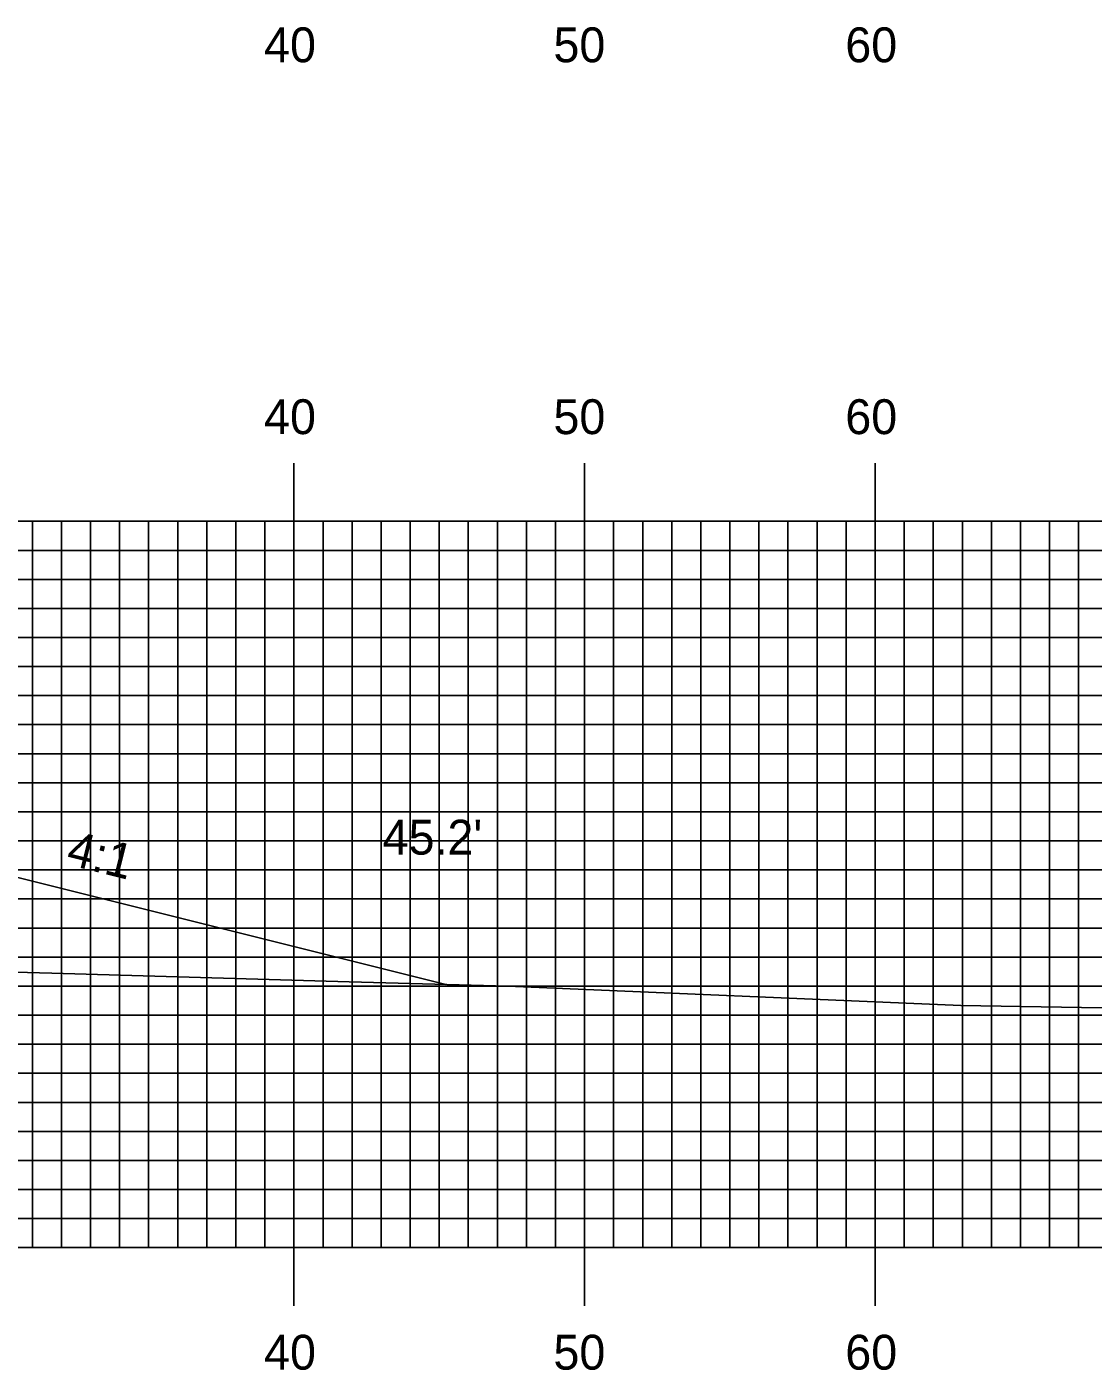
# Model space of a CAD drawing. Extents: x 1772809 to 1773153, y 442591 to 442811.
# Drawn here: x 1773005.93 to 1773042.62, y 442694.45 to 442740.68 of the extents above; entities that cross this region are included whole.
import ezdxf

# ---------------------------------------------------------------- set-up
doc = ezdxf.new("R2010")
doc.units = 0
for name, color, linetype in [('ANNOTATION', 7, 'Continuous'), ('D_Roadway_Centerline', 7, 'Continuous'), ('D_Roadway_SlopeLines', 7, 'Continuous'), ('D_Text_Standard', 7, 'Continuous'), ('H_V ANNOTATION', 7, 'Continuous'), ('MAJOR', 7, 'Continuous'), ('MINOR', 7, 'Continuous'), ('S_Roadway_Centerline', 7, 'Continuous')]:
    doc.layers.add(name, color=color, linetype=linetype)

msp = doc.modelspace()

# ---------------------------------------------------------------- linework, layer by layer
at = {"layer": 'D_Roadway_Centerline'}
msp.add_lwpolyline([(1772939.158, 442710.043), (1772939.401, 442710.104), (1772943.12, 442711.034), (1772944.769, 442711.446), (1772944.946, 442711.49), (1772955.12, 442714.034), (1772963.12, 442714.354), (1772975.119, 442714.594), (1772987.12, 442714.354), (1772995.12, 442714.034), (1773005.294, 442711.49), (1773020.347, 442707.727)], dxfattribs=at)
at = {"layer": 'D_Roadway_SlopeLines'}
msp.add_lwpolyline([(1772995.12, 442714.034), (1773005.294, 442711.49), (1773020.347, 442707.727)], dxfattribs=at)
at = {"layer": 'MAJOR'}
for p, q in [((1773015.12, 442725.669), (1773015.12, 442723.665)), ((1773025.12, 442725.669), (1773025.12, 442723.665)), ((1773035.12, 442725.669), (1773035.12, 442723.665)), ((1772835.12, 442723.665), (1773115.12, 442723.665)), ((1772835.12, 442723.665), (1773115.12, 442723.665)), ((1773015.12, 442698.665), (1773015.12, 442723.665)), ((1773025.12, 442698.665), (1773025.12, 442723.665)), ((1773035.12, 442698.665), (1773035.12, 442723.665)), ((1772835.12, 442718.665), (1773115.12, 442718.665)), ((1772835.12, 442713.665), (1773115.12, 442713.665)), ((1772835.12, 442708.665), (1773115.12, 442708.665)), ((1772835.12, 442703.665), (1773115.12, 442703.665)), ((1772835.12, 442698.665), (1773115.12, 442698.665)), ((1772835.12, 442698.665), (1773115.12, 442698.665)), ((1773015.12, 442696.661), (1773015.12, 442698.665)), ((1773025.12, 442696.661), (1773025.12, 442698.665)), ((1773035.12, 442696.661), (1773035.12, 442698.665))]:
    msp.add_line(p, q, dxfattribs=at)
at = {"layer": 'MINOR'}
for p, q in [((1773006.12, 442698.665), (1773006.12, 442723.665)), ((1773007.12, 442698.665), (1773007.12, 442723.665)), ((1773008.12, 442698.665), (1773008.12, 442723.665)), ((1773009.12, 442698.665), (1773009.12, 442723.665)), ((1773010.12, 442698.665), (1773010.12, 442723.665)), ((1773011.12, 442698.665), (1773011.12, 442723.665)), ((1773012.12, 442698.665), (1773012.12, 442723.665)), ((1773013.12, 442698.665), (1773013.12, 442723.665)), ((1773014.12, 442698.665), (1773014.12, 442723.665)), ((1773016.12, 442698.665), (1773016.12, 442723.665)), ((1773017.12, 442698.665), (1773017.12, 442723.665)), ((1773018.12, 442698.665), (1773018.12, 442723.665)), ((1773019.12, 442698.665), (1773019.12, 442723.665)), ((1773020.12, 442698.665), (1773020.12, 442723.665)), ((1773021.12, 442698.665), (1773021.12, 442723.665)), ((1773022.12, 442698.665), (1773022.12, 442723.665)), ((1773023.12, 442698.665), (1773023.12, 442723.665)), ((1773024.12, 442698.665), (1773024.12, 442723.665)), ((1773026.12, 442698.665), (1773026.12, 442723.665)), ((1773027.12, 442698.665), (1773027.12, 442723.665)), ((1773028.12, 442698.665), (1773028.12, 442723.665)), ((1773029.12, 442698.665), (1773029.12, 442723.665)), ((1773030.12, 442698.665), (1773030.12, 442723.665)), ((1773031.12, 442698.665), (1773031.12, 442723.665)), ((1773032.12, 442698.665), (1773032.12, 442723.665)), ((1773033.12, 442698.665), (1773033.12, 442723.665)), ((1773034.12, 442698.665), (1773034.12, 442723.665)), ((1773036.12, 442698.665), (1773036.12, 442723.665)), ((1773037.12, 442698.665), (1773037.12, 442723.665)), ((1773038.12, 442698.665), (1773038.12, 442723.665)), ((1773039.12, 442698.665), (1773039.12, 442723.665)), ((1773040.12, 442698.665), (1773040.12, 442723.665)), ((1773041.12, 442698.665), (1773041.12, 442723.665)), ((1773042.12, 442698.665), (1773042.12, 442723.665)), ((1772835.12, 442722.665), (1773115.12, 442722.665)), ((1772835.12, 442721.665), (1773115.12, 442721.665)), ((1772835.12, 442720.665), (1773115.12, 442720.665)), ((1772835.12, 442719.665), (1773115.12, 442719.665)), ((1772835.12, 442717.665), (1773115.12, 442717.665)), ((1772835.12, 442716.665), (1773115.12, 442716.665)), ((1772835.12, 442715.665), (1773115.12, 442715.665)), ((1772835.12, 442714.665), (1773115.12, 442714.665)), ((1772835.12, 442712.665), (1773115.12, 442712.665)), ((1772835.12, 442711.665), (1773115.12, 442711.665)), ((1772835.12, 442710.665), (1773115.12, 442710.665)), ((1772835.12, 442709.665), (1773115.12, 442709.665)), ((1772835.12, 442707.665), (1773115.12, 442707.665)), ((1772835.12, 442706.665), (1773115.12, 442706.665)), ((1772835.12, 442705.665), (1773115.12, 442705.665)), ((1772835.12, 442704.665), (1773115.12, 442704.665)), ((1772835.12, 442702.665), (1773115.12, 442702.665)), ((1772835.12, 442701.665), (1773115.12, 442701.665)), ((1772835.12, 442700.665), (1773115.12, 442700.665)), ((1772835.12, 442699.665), (1773115.12, 442699.665))]:
    msp.add_line(p, q, dxfattribs=at)
at = {"layer": 'S_Roadway_Centerline'}
msp.add_lwpolyline([(1772930.628, 442710.207), (1772936.627, 442710.11), (1772943.848, 442709.921), (1772960.001, 442709.334), (1772970.86, 442709.165), (1772972.293, 442709.098), (1772973.509, 442709.034), (1772991.332, 442708.548), (1772994.16, 442708.457), (1772994.352, 442708.455), (1772994.581, 442708.446), (1773006.783, 442708.11), (1773017.015, 442707.813), (1773019.541, 442707.75), (1773022.485, 442707.665), (1773038.067, 442706.998), (1773042.223, 442706.935), (1773048.141, 442706.881)], dxfattribs=at)

# ---------------------------------------------------------------- texts
at = {"layer": 'ANNOTATION'}
msp.add_text('4:1', height=1.2, rotation=345.9635, dxfattribs=at).set_placement((1773007.239, 442711.866))
at = {"layer": 'D_Text_Standard'}
msp.add_text("45.2'", height=1.2, dxfattribs=at).set_placement((1773018.171, 442712.193))
at = {"layer": 'H_V ANNOTATION'}
for s, p in [('40', (1773014.092, 442739.465)), ('50', (1773024.049, 442739.465)), ('60', (1773034.092, 442739.465)), ('40', (1773014.092, 442726.665)), ('50', (1773024.049, 442726.665)), ('60', (1773034.092, 442726.665)), ('40', (1773014.092, 442694.465)), ('50', (1773024.049, 442694.465)), ('60', (1773034.092, 442694.465))]:
    msp.add_text(s, height=1.2, dxfattribs=at).set_placement(p)

doc.saveas('drawing.dxf')
